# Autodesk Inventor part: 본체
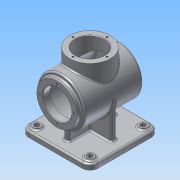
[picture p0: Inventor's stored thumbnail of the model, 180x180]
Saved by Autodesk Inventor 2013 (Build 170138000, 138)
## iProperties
Created: 2015-07
Part Number: 본체
Material: 알루미늄 6061
Document SubType Name: Modeling
Designer: Administrator
Density: 2.71 g/cm^3
Mass: 1277.62 g
Surface Area: 1267.64 cm^2
Volume: 471.447 cm^3
Author: Administrator
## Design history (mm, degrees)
sketch "스케치1"
  geometry: L1 (-50, -65)-(50, -65); L2 (65, -50)-(65, 50); L3 (50, 65)-(-50, 65); L4 (-65, 50)-(-65, -50); L5 (-65, -65)-(65, 65); L6 (65, -65)-(-65, 65); C1 r 7.5 at (-50, 50); C2 r 7.5 at (50, 50); C3 r 7.5 at (-50, -50); C4 r 7.5 at (50, -50); A1 r 15 centre (-50, 50) between (-50, 65) and (-65, 50); A2 r 15 centre (-50, -50) between (-65, -50) and (-50, -65); A3 r 15 centre (50, -50) between (50, -65) and (65, -50); A4 r 15 centre (50, 50) between (65, 50) and (50, 65); 3 further points
  constraints: 12 end point, 8 centre point, 8 point on circle, 8 point on line, 8 tangent, 5 equal radius, 3 midpoint, 2 horizontal alignment, 2 parallel, 2 vertical alignment, 1 coincident, 1 horizontal, 1 perpendicular
  dimensions: "d0" = 130 distance of L5.end L6.end; "d2" = 130 distance of L6.start L5.end; "d3" = 15 radius of A1; "d4" = 15 diameter of C1; "d5" = 15 diameter of C2; "d6" = 100 distance of C2.centre C1.centre; "d7" = 50 horizontal distance of point (0, 0) C1.centre; "d8" = 100 distance of C3.centre C1.centre; "d9" = 50 horizontal distance of C1.centre point (0, 0)
extrude "돌출1" new body sketch "스케치1" distance "d10" = 10; taper "d11" = 0 deg
extrude "돌출2" join sketch "스케치1" distance "d12" = 3; taper "d13" = 0 deg
hole "구멍1" diameter "d16" = 10; stored, may be unused: countersink angle "d20" = 90 deg, drill point angle "d22" = 0 deg; dims "d14" = 10, "d15" = 10, "d17" = 6, "d18" = 4, "d19" = 2, "d21" = 8
hole "구멍2" diameter "d25" = 10; stored, may be unused: countersink angle "d29" = 90 deg, drill point angle "d31" = 0 deg; dims "d23" = 10, "d24" = 10, "d26" = 6, "d27" = 4, "d28" = 2, "d30" = 8
hole "구멍3" diameter "d34" = 10; stored, may be unused: countersink angle "d38" = 90 deg, drill point angle "d40" = 0 deg; dims "d32" = 10, "d33" = 10, "d35" = 6, "d36" = 4, "d37" = 2, "d39" = 8
hole "구멍4" diameter "d43" = 10; stored, may be unused: countersink angle "d47" = 90 deg, drill point angle "d49" = 0 deg; dims "d41" = 10, "d42" = 10, "d44" = 6, "d45" = 4, "d46" = 2, "d48" = 8
sketch "스케치2"
  geometry: L1 (50, -10)-(-50, -10) reference; C1 r 45 at (0, 68); 1 further point
  constraints: 1 centre point
  dimensions: "d51" = 90 diameter of C1; "d53" = 78 distance from line of C1.centre L1
extrude "돌출3" join sketch "스케치2" stored distance "d54" = 110; taper "d55" = 0 deg
sketch "스케치3"
  geometry: C1 r 45 at (0, 0) reference; C2 r 38 at (0, 0); 1 further point
  constraints: 1 centre point, 1 coincident
  dimensions: "d56" = 76 diameter of C2
extrude "돌출4" join sketch "스케치3" distance "d58" = 7; taper "d59" = 0 deg
hole "구멍5" diameter "d62" = 54; stored, may be unused: countersink angle "d66" = 90 deg, drill point angle "d68" = 0 deg; dims "d60" = 10, "d61" = 10, "d63" = 6, "d64" = 4, "d65" = 2, "d67" = 14
hole "구멍6" diameter "d71" = 80; stored, may be unused: countersink angle "d75" = 90 deg, drill point angle "d77" = 0 deg; dims "d69" = 10, "d70" = 10, "d72" = 6, "d73" = 4, "d74" = 2, "d76" = 96
node "작업 평면1"
sketch "스케치4"
  geometry: C1 r 38 at (0, 0); 1 further point
  constraints: 1 centre point, 1 coincident
  dimensions: "d79" = 76 diameter of C1
extrude "돌출5" join sketch "스케치4" stored distance "d81" = 7; taper "d82" = 0 deg
hole "구멍7" diameter "d85" = 54; stored, may be unused: countersink angle "d89" = 90 deg, drill point angle "d91" = 0 deg; dims "d83" = 10, "d84" = 10, "d86" = 6, "d87" = 4, "d88" = 2, "d90" = 43.25
sketch "스케치5"
  geometry: L1 (65, 50)-(65, -50) reference; L2 (-5, 5)-(-5, 45); L3 (-5, 45)-(5, 45); L4 (5, 45)-(5, 5); L5 (5, 5)-(45, 5); L6 (45, 5)-(45, -5); L7 (45, -5)-(5, -5); L8 (5, -5)-(5, -45); L9 (5, -45)-(-5, -45); L10 (-5, -45)-(-5, -5); L11 (-5, -5)-(-45, -5); L12 (-45, -5)-(-45, 5); L13 (-45, 5)-(-5, 5); 5 further points
  constraints: 24 end point, 9 parallel, 4 midpoint, 3 perpendicular, 2 horizontal alignment, 2 vertical alignment
  dimensions: "d92" = 10 distance of L2.end L3.end; "d94" = 10 distance of L5.end L6.end; "d95" = 10 distance of L8.end L9.end; "d96" = 10 distance of L11.end L12.end; "d97" = 90 distance between parallel lines of L6 L12; "d98" = 45 horizontal distance of point (0, 0) L12.end; "d99" = 90 distance between parallel lines of L9 L3; "d100" = 45 distance from line of L9 point (0, 0)
extrude "돌출6" join sketch "스케치5" stored distance "d101" = 7; taper "d102" = 0 deg
sketch "스케치6"
  geometry: C1 r 45 at (0, 0) reference; 2 further points
  constraints: 1 coincident, 1 other
feature "엠보싱1" sketch "스케치6" dims "d0" = 130, "d2" = 130, "d3" = 15, "d4" = 15, "d5" = 15, "d6" = 100, "d7" = 50, "d8" = 100, "d9" = 50, "d103" = 0.5, "d104" = 0
sketch "스케치7" dims "d105" = 64
  geometry: C1 r 27 at (0, 0) reference; C2 r 38 at (0, 0) reference; 3 further points
  constraints: 2 vertical alignment, 1 coincident, 2 other
hole "구멍8" sketch "스케치7" at (0, 32) diameter "d107" = 3.242; stored, may be unused: countersink angle "d111" = 90 deg, drill point angle "d113" = 118 deg; dims "d108" = 8, "d109" = 4, "d110" = 2, "d112" = 10
sketch "스케치8" dims "d117" = 64
  geometry: C1 r 38 at (0, 0) reference; C2 r 27 at (0, 0) reference; 2 further points
  constraints: 2 vertical alignment, 1 coincident, 2 other
hole "구멍9" sketch "스케치8" at (0, 32) diameter "d119" = 3.242; stored, may be unused: countersink angle "d123" = 90 deg, drill point angle "d125" = 118 deg; dims "d120" = 8, "d121" = 4, "d122" = 2, "d124" = 10
fillet "모깎기1" dims "d129" = 3
fillet "모깎기2" dims "d130" = 3
fillet "모깎기3" dims "d131" = 3
fillet "모깎기4" dims "d132" = 3
fillet "모깎기5" dims "d133" = 3
fillet "모깎기6" dims "d134" = 3
fillet "모깎기7" dims "d135" = 3
fillet "모깎기8" dims "d136" = 3
fillet "모깎기9" dims "d137" = 3
chamfer "모따기1" distance "d138" = 1; stored, may be unused: second distance "d139" = 2, angle "d140" = 45 deg
node "솔리드1"
pattern_circular "원형 패턴1" dims angle "d115" = 360 deg
pattern_circular "원형 패턴2" dims angle "d127" = 360 deg
